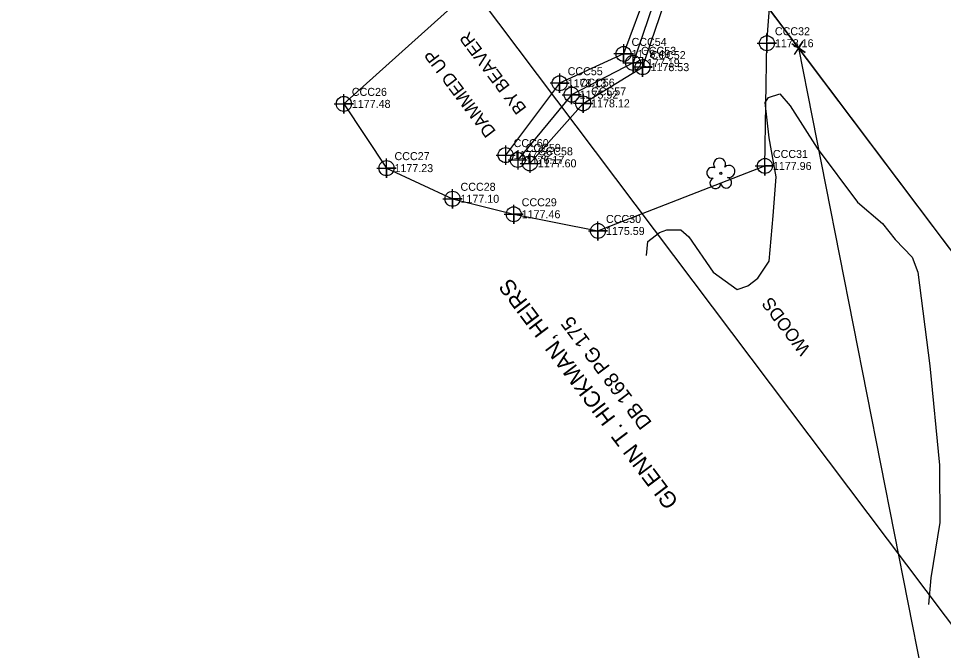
# Model space of a CAD drawing. Extents: x 1262092 to 1264624, y 774970 to 778314.
# Drawn here: x 1262432.5 to 1262721.5, y 777094.1 to 777291.5 of the extents above; entities that cross this region are included whole.
import ezdxf

# ---------------------------------------------------------------- set-up
doc = ezdxf.new("R2010")
doc.units = 0
for name, color, linetype in [('COGO Default Parcel', 7, 'Continuous'), ('Cogo Default Point CELL', 7, 'Continuous'), ('COGO Default Point Elevation', 7, 'Continuous'), ('COGO Default Point Number', 7, 'Continuous'), ('Exist Boundary City Limits', 7, 'Continuous'), ('Exist DTM Breakline', 7, 'Continuous'), ('Exist DTM Breakline Cogo Elevation', 7, 'Continuous'), ('Exist DTM Breakline Cogo Number', 7, 'Continuous'), ('Exist DTM Breakline Cogo Point CELL', 7, 'Continuous'), ('Exist DTM Regular Point CELL', 7, 'Continuous'), ('Exist Horizontal Alignment Tick Small', 7, 'Continuous'), ('Exist Hydro Jurisdictional Stream or Body of Water', 7, 'Continuous'), ('Exist Hydro Jurisdictional Stream or Body of Water Text', 7, 'Continuous'), ('Exist Hydro Stream or Body of Water Cogo Elevation', 7, 'Continuous'), ('Exist Hydro Stream or Body of Water Cogo Number', 7, 'Continuous'), ('Exist Hydro Stream or Body of Water Cogo Point CELL', 7, 'Continuous'), ('Exist Hydro Swamp or Marsh', 7, 'Continuous'), ('Exist Property Corner CELL', 7, 'Continuous'), ('Exist Property Deed Book Text', 7, 'Continuous'), ('Exist Property Line', 7, 'Continuous'), ('Exist Property Owner Text', 7, 'Continuous'), ('Exist Right of Way Line', 7, 'Continuous'), ('Exist Vegetation Woods Line Text', 7, 'Continuous'), ('Prop Conc 5in Monolithic Keyed In Island', 7, 'Continuous')]:
    doc.layers.add(name, color=color, linetype=linetype)

msp = doc.modelspace()

# ---------------------------------------------------------------- linework, layer by layer
at = {"layer": 'COGO Default Parcel'}
msp.add_line((1263155.86, 776528.63), (1262121.77, 777902.18), dxfattribs=at)
at = {"layer": 'Cogo Default Point CELL'}
for points in [[(1262584.71, 777251.81), (1262584.71, 777248.81)], [(1262581.71, 777248.81), (1262584.71, 777248.81)], [(1262584.71, 777248.81), (1262587.71, 777248.81)], [(1262584.71, 777248.81), (1262584.71, 777245.81)], [(1262588.49, 777250.32), (1262588.49, 777247.32)], [(1262592.27, 777249.24), (1262592.27, 777246.24)], [(1262585.49, 777247.32), (1262588.49, 777247.32)], [(1262588.49, 777247.32), (1262591.49, 777247.32)], [(1262588.49, 777247.32), (1262588.49, 777244.32)], [(1262589.27, 777246.24), (1262592.27, 777246.24)], [(1262592.27, 777246.24), (1262595.27, 777246.24)], [(1262592.27, 777246.24), (1262592.27, 777243.24)]]:
    msp.add_lwpolyline(points, dxfattribs=at)
for centre in [(1262584.71, 777248.81), (1262588.49, 777247.32), (1262592.27, 777246.24)]:
    msp.add_circle(centre, 2.34, dxfattribs=at)
at = {"layer": 'Exist Boundary City Limits'}
msp.add_line((1263013.39, 776834.66), (1262172.78, 777950.69), dxfattribs=at)
at = {"layer": 'Exist DTM Breakline'}
for points in [[(1262668.13, 777358.05), (1262663.03, 777363.39), (1262633.78, 777342.25), (1262631.85, 777337.86), (1262637.14, 777329.72), (1262629.16, 777300.98), (1262621.57, 777280.42), (1262601.6, 777271.26), (1262584.71, 777248.81)], [(1262592.27, 777246.24), (1262608.93, 777264.97), (1262627.51, 777276.29), (1262636.86, 777303.76), (1262645.3, 777327.77), (1262647.33, 777333.68), (1262667.11, 777351.06), (1262669.13, 777357)]]:
    msp.add_lwpolyline(points, dxfattribs=at)
at = {"layer": 'Exist DTM Breakline Cogo Point CELL'}
for points in [[(1262621.57, 777283.42), (1262621.57, 777277.42), (1262621.57, 777280.42), (1262624.57, 777280.42), (1262618.57, 777280.42)], [(1262627.51, 777279.29), (1262627.51, 777273.29), (1262627.51, 777276.29), (1262630.51, 777276.29), (1262624.51, 777276.29)], [(1262601.6, 777274.26), (1262601.6, 777268.26), (1262601.6, 777271.26), (1262604.6, 777271.26), (1262598.6, 777271.26)], [(1262608.93, 777267.97), (1262608.93, 777261.97), (1262608.93, 777264.97), (1262611.93, 777264.97), (1262605.93, 777264.97)]]:
    msp.add_lwpolyline(points, dxfattribs=at)
for centre in [(1262621.57, 777280.42), (1262627.51, 777276.29), (1262601.6, 777271.26), (1262608.93, 777264.97)]:
    msp.add_circle(centre, 2.34, dxfattribs=at)
at = {"layer": 'Exist DTM Regular Point CELL'}
for points in [[(1262663.36, 777283.75), (1262669.36, 777283.75), (1262666.36, 777283.75), (1262666.36, 777280.75), (1262666.36, 777286.75)], [(1262531.16, 777264.81), (1262537.16, 777264.81), (1262534.16, 777264.81), (1262534.16, 777261.81), (1262534.16, 777267.81)], [(1262662.73, 777245.42), (1262668.73, 777245.42), (1262665.73, 777245.42), (1262665.73, 777242.42), (1262665.73, 777248.42)], [(1262544.49, 777244.74), (1262550.49, 777244.74), (1262547.49, 777244.74), (1262547.49, 777241.74), (1262547.49, 777247.74)], [(1262565.12, 777235.16), (1262571.12, 777235.16), (1262568.12, 777235.16), (1262568.12, 777232.16), (1262568.12, 777238.16)], [(1262584.24, 777230.33), (1262590.24, 777230.33), (1262587.24, 777230.33), (1262587.24, 777227.33), (1262587.24, 777233.33)], [(1262610.58, 777225.11), (1262616.58, 777225.11), (1262613.58, 777225.11), (1262613.58, 777222.11), (1262613.58, 777228.11)]]:
    msp.add_lwpolyline(points, dxfattribs=at)
for centre in [(1262666.36, 777283.75), (1262534.16, 777264.81), (1262547.49, 777244.74), (1262665.73, 777245.42), (1262568.12, 777235.16), (1262587.24, 777230.33), (1262613.58, 777225.11)]:
    msp.add_circle(centre, 2.34, dxfattribs=at)
at = {"layer": 'Exist Horizontal Alignment Tick Small'}
msp.add_line((1262651.94, 777243.12), (1262651.94, 777243.12), dxfattribs=at)
msp.add_circle((1262651.94, 777243.12), 0.326, dxfattribs=at)
for centre, radius, start, end in [((1262649.34, 777243.28), 1.73, 62.6636, 279.3457), ((1262651.56, 777246), 1.86, 330.1651, 219.7134), ((1262654.49, 777243.71), 1.9, 257.1011, 134.1999), ((1262650.24, 777240), 1.69, 111.5671, 6.231), ((1262653.61, 777240.23), 1.7, 181.2822, 74.56)]:
    msp.add_arc(centre, radius, start, end, dxfattribs=at)
at = {"layer": 'Exist Hydro Jurisdictional Stream or Body of Water'}
msp.add_lwpolyline([(1262665.03, 777358.01), (1262637.64, 777338.85), (1262641.05, 777329.08), (1262632.29, 777300.33), (1262624.53, 777277.63), (1262605.34, 777267.69), (1262588.49, 777247.32)], dxfattribs=at)
at = {"layer": 'Exist Hydro Stream or Body of Water Cogo Point CELL'}
for points in [[(1262621.53, 777277.63), (1262627.53, 777277.63), (1262624.53, 777277.63), (1262624.53, 777274.63), (1262624.53, 777280.63)], [(1262602.34, 777267.69), (1262608.34, 777267.69), (1262605.34, 777267.69), (1262605.34, 777264.69), (1262605.34, 777270.69)]]:
    msp.add_lwpolyline(points, dxfattribs=at)
for centre in [(1262624.53, 777277.63), (1262605.34, 777267.69)]:
    msp.add_circle(centre, 2.34, dxfattribs=at)
at = {"layer": 'Exist Hydro Swamp or Marsh'}
msp.add_lwpolyline([(1262604.75, 777391.3), (1262604.82, 777363.34), (1262598.8, 777322.88), (1262534.16, 777264.81), (1262547.49, 777244.74), (1262568.12, 777235.16), (1262587.24, 777230.33), (1262613.58, 777225.11), (1262665.73, 777245.42), (1262666.36, 777283.75), (1262668.89, 777316.79), (1262679.78, 777345.65), (1262667.11, 777351.06)], dxfattribs=at)
at = {"layer": 'Exist Property Corner CELL'}
msp.add_line((1262676.24, 777282.27), (1262676.24, 777282.27), dxfattribs=at)
msp.add_lwpolyline([(1262674.17, 777283.66), (1262678.32, 777280.88), (1262676.24, 777282.27), (1262677.63, 777284.34), (1262674.85, 777280.19)], dxfattribs=at)
at = {"layer": 'Exist Property Line'}
msp.add_line((1262676.24, 777282.27), (1262789.81, 776707.27), dxfattribs=at)
at = {"layer": 'Exist Right of Way Line'}
msp.add_line((1262172.78, 777950.69), (1263224.83, 776553.94), dxfattribs=at)
at = {"layer": 'Prop Conc 5in Monolithic Keyed In Island'}
msp.add_lwpolyline([(1262628.69, 777217.44), (1262629.18, 777221.87), (1262632.83, 777224.68), (1262635.07, 777225.47), (1262639.42, 777225.45), (1262641.93, 777223.26), (1262649.55, 777212.24), (1262657.12, 777206.85), (1262660.37, 777207.95), (1262663.56, 777210.42), (1262667.05, 777215.68), (1262668.3, 777229.88), (1262669.3, 777242.03), (1262667.06, 777254.25), (1262665.86, 777265.2), (1262666.9, 777266.77), (1262670.42, 777267.99), (1262673.67, 777264.23), (1262682.08, 777250.96), (1262694.67, 777234.11), (1262702.51, 777227.41), (1262706.4, 777222.45), (1262711.73, 777216.97), (1262713.52, 777212.2), (1262717.24, 777182.97), (1262720.3, 777152.01), (1262720.44, 777134.07), (1262717.58, 777116.72), (1262716.9, 777108.42)], dxfattribs=at)

# ---------------------------------------------------------------- texts
at = {"layer": 'COGO Default Point Elevation'}
for s, p in [('1177.32', (1262587.21, 777247.56)), ('1176.17', (1262590.99, 777246.07)), ('1177.60', (1262594.77, 777244.99))]:
    msp.add_text(s, height=2.5, dxfattribs=at).set_placement(p)
at = {"layer": 'COGO Default Point Number'}
for s, p in [('CCC60', (1262587.21, 777251.31)), ('CCC59', (1262590.99, 777249.82)), ('CCC58', (1262594.77, 777248.74))]:
    msp.add_text(s, height=2.5, dxfattribs=at).set_placement(p)
at = {"layer": 'Exist DTM Breakline Cogo Elevation'}
for s, p in [('1178.40', (1262624.07, 777279.17)), ('1178.53', (1262630.01, 777275.04)), ('1178.13', (1262604.1, 777270.01)), ('1178.12', (1262611.43, 777263.72))]:
    msp.add_text(s, height=2.5, dxfattribs=at).set_placement(p)
at = {"layer": 'Exist DTM Breakline Cogo Number'}
for s, p in [('CCC54', (1262624.07, 777282.92)), ('CCC52', (1262630.01, 777278.79)), ('CCC55', (1262604.1, 777273.76)), ('CCC57', (1262611.43, 777267.47))]:
    msp.add_text(s, height=2.5, dxfattribs=at).set_placement(p)
at = {"layer": 'Exist Hydro Jurisdictional Stream or Body of Water Text'}
for s, p in [('BY BEAVER', (1262591.43, 777263.45)), ('DAMMED UP ', (1262581.85, 777256.23))]:
    msp.add_text(s, height=4, rotation=126.9874, dxfattribs=at).set_placement(p)
at = {"layer": 'Exist Hydro Stream or Body of Water Cogo Elevation'}
for s, p in [('1178.16', (1262668.86, 777282.5)), ('1177.19', (1262627.03, 777276.38)), ('1175.92', (1262607.84, 777266.44)), ('1177.48', (1262536.66, 777263.56)), ('1177.23', (1262549.99, 777243.49)), ('1177.96', (1262668.23, 777244.17)), ('1177.10', (1262570.62, 777233.91)), ('1177.46', (1262589.74, 777229.08)), ('1175.59', (1262616.08, 777223.86))]:
    msp.add_text(s, height=2.5, dxfattribs=at).set_placement(p)
at = {"layer": 'Exist Hydro Stream or Body of Water Cogo Number'}
for s, p in [('CCC32', (1262668.86, 777286.25)), ('CCC53', (1262627.03, 777280.13)), ('CCC56', (1262607.84, 777270.19)), ('CCC26', (1262536.66, 777267.31)), ('CCC27', (1262549.99, 777247.24)), ('CCC31', (1262668.23, 777247.92)), ('CCC28', (1262570.62, 777237.66)), ('CCC29', (1262589.74, 777232.83)), ('CCC30', (1262616.08, 777227.61))]:
    msp.add_text(s, height=2.5, dxfattribs=at).set_placement(p)
at = {"layer": 'Exist Property Deed Book Text'}
msp.add_text('DB 168 PG 175', height=4.5, rotation=126.9874, dxfattribs=at).set_placement((1262630.6, 777165.25))
at = {"layer": 'Exist Property Owner Text'}
msp.add_text('GLENN T. HICKMAN, HEIRS', height=5, rotation=126.9874, dxfattribs=at).set_placement((1262638.95, 777140.62))
at = {"layer": 'Exist Vegetation Woods Line Text'}
msp.add_text('WOODS', height=4, rotation=126.9874, dxfattribs=at).set_placement((1262680.17, 777188.19))

doc.saveas('drawing.dxf')
